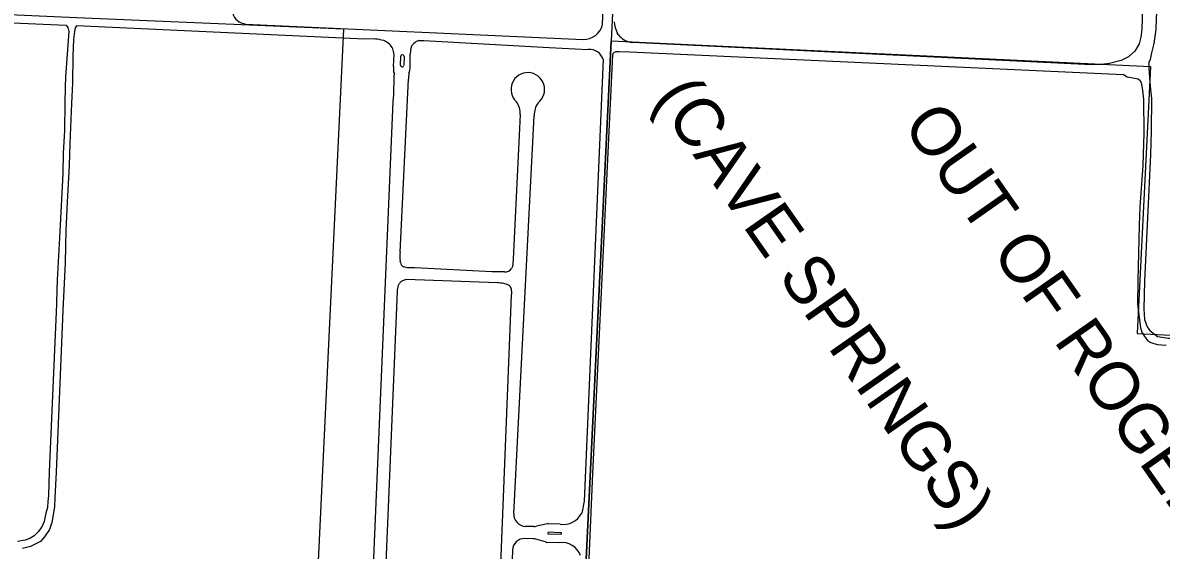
# Model space of a CAD drawing. Extents: x 0 to 712119, y 0 to 761125.
# Drawn here: x 660107 to 662915, y 714980 to 716281 of the extents above; entities that cross this region are included whole.
import ezdxf

# ---------------------------------------------------------------- set-up
doc = ezdxf.new("R2010")
doc.units = 0
for name, color, linetype in [('city boundary', 7, 'Continuous'), ('ISLANDS', 7, 'Continuous'), ('PAVED ROADS', 7, 'Continuous'), ('Priority 18', 7, 'Continuous')]:
    doc.layers.add(name, color=color, linetype=linetype)

msp = doc.modelspace()

# ---------------------------------------------------------------- linework, layer by layer
at = {"layer": 'city boundary'}
msp.add_lwpolyline([(669278.8, 710645.8), (667929.4, 710709.9), (666619.7, 710772.2), (665299.6, 710838.1), (663981.9, 710903.9), (662646.3, 710970.6), (662691.5, 712202.3), (661809.5, 712250.3), (661859.2, 713252.5), (661419.4, 713275.7), (661434.7, 713608.9), (660776, 713641), (660836.8, 714952.6), (660899.3, 716265.3), (660240, 716293.5), (660074.3, 716300.6)], dxfattribs=at)
at = {"layer": 'ISLANDS'}
msp.add_lwpolyline([(661495, 714923.1), (661558.5, 716237.1), (662888.7, 716173.6), (662856, 715514.6), (664191, 715448.9), (665185.7, 715399.9), (665169.4, 715068.9), (665500.5, 715052.6), (665517.3, 715383.6), (665517.3, 715383.6), (665550.9, 716046.6), (665618, 717367.5), (666949.9, 717306.3), (667149.6, 717295.4), (667129.4, 716895.9), (666929.7, 716906.8), (666883, 715983.1), (666813.6, 714653)], dxfattribs=at)
at = {"layer": 'PAVED ROADS'}
for points in [[(661537.1, 716276.8), (661587.1, 717501.6)], [(662883.7, 716722.8), (662883, 716695.3), (662881.8, 716641.1), (662874.9, 716506.2), (662867.5, 716266), (662864.7, 716245.5), (662860.9, 716229.5), (662850.4, 716211.7), (662834.8, 716197.4), (662816.3, 716188), (662787.3, 716180.7), (662767.1, 716178.2), (662743.6, 716177.7), (661610.7, 716232.7)], [(662922.6, 716699.4), (662903, 716290.5), (662901.7, 716264.8), (662897.2, 716230.5), (662891.3, 716207.5), (662888.1, 716190.8), (662884.5, 716183.2), (662884.5, 716169.7), (662887.2, 716134.9), (662889, 716116.9), (662890.8, 716094.8), (662890.7, 716014.8), (662888.5, 715956.5), (662873.9, 715643.5), (662872.6, 715575.4), (662873.9, 715549.5), (662880.1, 715531.2), (662886.8, 715522.2), (662906.1, 715507.1), (662933.3, 715503.5), (662943, 715503.5), (663698.8, 715469)], [(660082.5, 716281.1), (660214.5, 716275.4), (660218, 716270), (660220.7, 716259.9), (660212.7, 716148), (660212.1, 716122.5), (660210.9, 716083.3), (660210, 716015.9), (660206.7, 715959.5), (660205.7, 715909.7), (660202.5, 715845.3), (660197.6, 715750.4), (660192.3, 715646.8), (660190.3, 715592.1), (660190.2, 715586.9), (660172.5, 715173.2), (660170.4, 715115.2), (660169.2, 715100.1), (660168.5, 715085.4), (660164.5, 715071), (660160, 715051.1), (660155, 715039), (660146, 715025.8), (660135.6, 715015.4), (660124.9, 715009), (660112.9, 715004.8), (660094.2, 715001.4)], [(660972.2, 716241.5), (660950.9, 716241.2), (660896.7, 716243.1), (660239.5, 716274.2), (660236.2, 716268.7), (660234.7, 716260.1), (660232.3, 716240.3), (660230.7, 716199.1), (660229.5, 716133.5), (660227.1, 716082.4), (660223.6, 715983.6), (660221.6, 715928.9), (660216.9, 715839.1), (660213.8, 715768.5), (660212.4, 715731.3), (660211.6, 715689.3), (660205.9, 715571.1), (660189.3, 715172.1), (660186, 715109.5), (660185.2, 715087.9), (660182.5, 715067.6), (660178.7, 715048.2), (660172.8, 715031.3), (660161, 715013.1), (660151, 715001.6), (660125.9, 714989.5), (660106.4, 714984.5)], [(660656.8, 716278.3), (661489.3, 716240.1)], [(661576, 716252.4), (661573.5, 716256.9)], [(660997.4, 716237.5), (660991.6, 716238.8)], [(661011.4, 716228.9), (661005.4, 716233.2)], [(661064.1, 716215.4), (661065, 716219.7)], [(661068.4, 716227.3), (661072, 716230.6)], [(661084.1, 716237.3), (661096.6, 716237.7), (661405.6, 716220.6), (661502, 716215.1)], [(661590.7, 716239.3), (661590.7, 716239.3)], [(661021.3, 716173.8), (661023.1, 716203.1)], [(661038.8, 716176.6), (661039.5, 716198.6)], [(661047.5, 716198.4), (661046.8, 716176.4), (661046.8, 716176.4)], [(661062.6, 716175.7), (661062.8, 716203.6)], [(661451.5, 713733.5), (661513, 715168.9), (661562.2, 716202.1), (661564.1, 716207.5), (661569.8, 716210.5), (661578.4, 716210.5), (661603.7, 716209.3), (662821.8, 716153.7), (662831.1, 716147.7), (662845, 716145.3), (662858.5, 716142.9), (662863.3, 716139.2), (662865.5, 716133), (662868.9, 716114.9), (662871.2, 716092.4), (662872.3, 716009.1), (662869.6, 715929.4), (662862.7, 715827.3), (662861, 715781.3), (662857.7, 715644.5), (662856.3, 715587.1), (662863.8, 715528.4), (662867.4, 715517.9), (662873.9, 715507.1), (662881.7, 715496.9), (662889.3, 715492.2), (662904.8, 715487.7), (662927.6, 715486.2)], [(661538.7, 716191.1), (661491.8, 715101.3), (661485.7, 715071.4)], [(661023.7, 716156.9), (661022, 716160.9)], [(661059.8, 716157.2), (661061.6, 716163.3)], [(661037.8, 715715.7), (661058.2, 716142.4)], [(660951.9, 714456.7), (661021.1, 716086.1)], [(661333.9, 716055.3), (661317, 715697.9)], [(661318.1, 715069.8), (661368.4, 716052.1)], [(661039, 715689.6), (661038.1, 715693.1)], [(661055, 715676.8), (661046.7, 715679.4)], [(661315.6, 715681.4), (661312.5, 715674.7)], [(661264.3, 715666.7), (661074.4, 715676.5)], [(661295.5, 715666.7), (661287.7, 715666.7)], [(661295.5, 715666.7), (661295.5, 715666.7), (661295.5, 715666.7)], [(661035.1, 715636.7), (661033.1, 715633.4)], [(661043.6, 715645), (661040.4, 715642.8)], [(661277.7, 715639.3), (661052.9, 715647.6)], [(661299.4, 715636.5), (661293.7, 715638)], [(661312.3, 715625.1), (661309.7, 715630.4)], [(661030.5, 715618.5), (660981.9, 714455.7)], [(661266.8, 714446.5), (661313, 715609.6)], [(661367.3, 715038.2), (661347.2, 715038.8)], [(661397.3, 715044.5), (661373.9, 715038.9)], [(661432.3, 715044.3), (661403.8, 715045.1)], [(661366.5, 715008.2), (661345.9, 715008.8)], [(661396.1, 715000.2), (661372.9, 715007.2)], [(661404.1, 715020.1), (661434.1, 715019.2)], [(661434.2, 715023.2), (661404.2, 715024.1), (661404.2, 715024.1)], [(661315.1, 714979.9), (661296.7, 714445.5)], [(661430.4, 714998.3), (661402.6, 714999.1)]]:
    msp.add_lwpolyline(points, dxfattribs=at)
for centre, radius, start, end in [((660660.1, 716314.7), 36.5, 195.8448, 264.7394), ((661489.5, 716289.3), 49.2, 269.7362, 345.2396), ((661628.6, 716287.5), 63, 183.0871, 209.0615), ((660971.1, 716162.9), 78.6, 74.9282, 89.2313), ((661625.1, 716292.3), 63.2, 219.1163, 237.0175), ((660976.7, 716190), 51.8, 56.3945, 66.4055), ((660982, 716199.9), 41.3, 4.3814, 44.5343), ((661148.8, 716200.6), 86.1, 170.0701, 177.9401), ((661082.8, 716216.4), 18.1, 143.1664, 169.7237), ((661090.2, 716212.1), 26, 103.5641, 134.5622), ((661505.9, 716181), 34.4, 17.1606, 96.4151), ((661620.3, 716296), 64, 242.4198, 261.4167), ((661043.5, 716198.5), 4, 358.0366, 178.0366), ((659442.1, 716178.4), 1581.7, 356.6554, 359.2198), ((661101.6, 716171.9), 80.4, 178.6919, 187.8579), ((661042.8, 716176.5), 4, 178.0358, 358.0366), ((661105.3, 716144.8), 47.1, 164.7259, 182.9185), ((660992.6, 716175.6), 70.1, 349.9223, 0.1025), ((661352.8, 716116.9), 41.5, 307.3965, 227.5721), ((661288.5, 716058.8), 45.5, 355.5584, 37.0586), ((661425.9, 716052.1), 57.5, 146.4278, 180.0023), ((661107.6, 715705.4), 70.6, 171.5811, 190.034), ((661050.5, 715690.2), 11.5, 183.1128, 250.65), ((661921, 715637.3), 607.1, 174.2797, 175.8378), ((661062.5, 715542.7), 134.3, 84.907, 93.2155), ((661270.2, 708044.8), 7621.9, 89.86788, 90.04383), ((661295.8, 715688.1), 21.4, 269.1102, 321.2884), ((661095.9, 715614.8), 65.4, 163.5289, 176.8067), ((661057.5, 715622.7), 26.4, 130.3053, 147.9253), ((661058.8, 715608.6), 39.4, 98.6417, 112.6836), ((661280.7, 715577.2), 62.2, 77.9423, 92.7546), ((661294.9, 715617), 20, 42.1028, 76.8989), ((661251.5, 715614.4), 61.7, 355.544, 10.046), ((661348.1, 715068.8), 30, 178.0366, 268.3017), ((661440.2, 715094.9), 51.2, 261.1635, 332.7016), ((661368.1, 715063.2), 25, 268.3017, 283.4032), ((661403.1, 715020.1), 25, 88.3017, 103.4032), ((661345, 714978.8), 30, 88.3017, 178.0366), ((661365.7, 714983.2), 25, 73.2587, 88.3017), ((661404.1, 715022.1), 2, 88.5667, 268.3017), ((661434.1, 715021.2), 2, 268.3017, 88.3017), ((661403.3, 715024.1), 25, 253.2587, 268.3017), ((661437.4, 714950.2), 48.6, 19.823, 98.2715)]:
    msp.add_arc(centre, radius, start, end, dxfattribs=at)
at = {"layer": 'Priority 18'}
msp.add_lwpolyline([(661697.4, 720091.7), (661670.9, 718874.5), (661622.1, 717551.1), (661558.5, 716237.1), (661495, 714923.1), (661434.7, 713608.9), (661373.4, 712274)], dxfattribs=at)

# ---------------------------------------------------------------- texts
at = {"layer": 'ISLANDS'}
for s, p in [('(CAVE SPRINGS)', (661661.2, 716095.2)), ('OUT OF ROGERS', (662275.1, 716029.7))]:
    msp.add_text(s, height=120, rotation=305, dxfattribs=at).set_placement(p)

doc.saveas('drawing.dxf')
